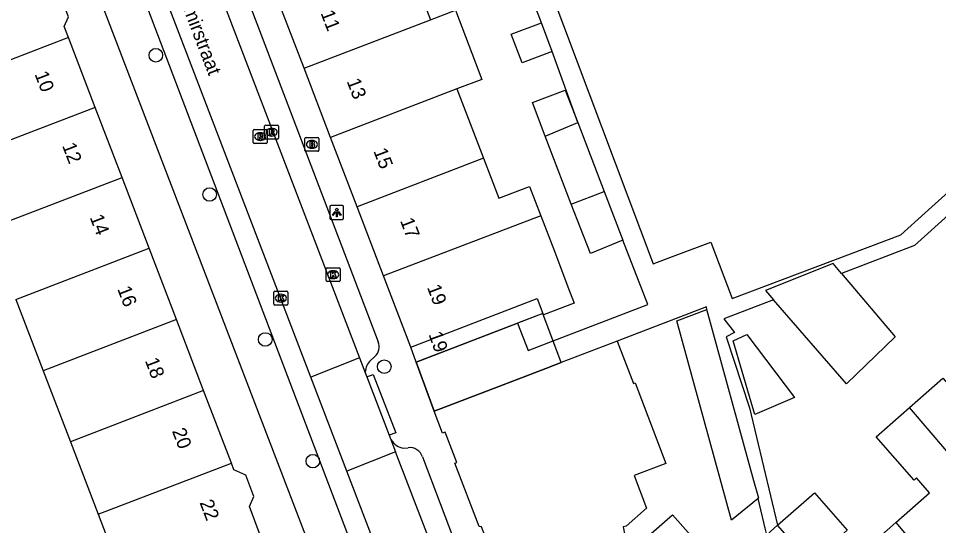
# Model space of a CAD drawing. Extents: x 159961 to 160856, y 382704 to 383353.
# Drawn here: x 160456.8 to 160523.1, y 383056 to 383092.5 of the extents above; entities that cross this region are included whole.
import ezdxf

# ---------------------------------------------------------------- set-up
doc = ezdxf.new("R2010")
doc.units = 0
for name, color, linetype in [('IMGEO_Boom', 7, 'Continuous'), ('IMGEO_Brandkraan', 7, 'Continuous'), ('IMGEO_Kolk', 7, 'Continuous'), ('IMGEO_Lichtpunt', 7, 'Continuous'), ('IMGEO_Openbare_ruimte_label', 7, 'Continuous'), ('IMGEO_Pand', 7, 'Continuous'), ('IMGEO_Pand_nummerreeks', 7, 'Continuous'), ('IMGEO_Pand_overbouw', 7, 'Continuous'), ('IMGEO_Rijbaan_lokaal_open', 7, 'Continuous'), ('IMGEO_Rioolput', 7, 'Continuous'), ('IMGEO_Voetpad_open', 7, 'Continuous')]:
    doc.layers.add(name, color=color, linetype=linetype)

msp = doc.modelspace()

# ---------------------------------------------------------------- linework, layer by layer
at = {"layer": 'IMGEO_Boom'}
for centre in [(160466.702, 383089.855), (160470.576, 383079.834), (160474.58, 383069.407), (160483.146, 383067.451), (160478.005, 383060.653)]:
    msp.add_circle(centre, 0.489, dxfattribs=at)
at = {"layer": 'IMGEO_Brandkraan'}
for p, q in [((160477.44, 383083.016), (160477.44, 383083.868)), ((160477.515, 383083.942), (160478.367, 383083.942)), ((160477.928, 383083.722), (160477.953, 383083.722)), ((160478.441, 383083.868), (160478.441, 383083.016)), ((160477.951, 383083.162), (160477.926, 383083.162)), ((160478.367, 383082.942), (160477.515, 383082.942))]:
    msp.add_line(p, q, dxfattribs=at)
for points in [[(160477.44, 383083.016), (160477.44, 383083.868)], [(160477.515, 383083.942), (160478.367, 383083.942)], [(160478.441, 383083.868), (160478.441, 383083.016)], [(160477.788, 383083.642), (160477.788, 383083.242), (160478.001, 383083.242)], [(160478.019, 383083.642), (160477.788, 383083.642)], [(160477.967, 383083.561), (160477.913, 383083.561), (160477.913, 383083.485)], [(160477.913, 383083.485), (160477.966, 383083.485)], [(160477.975, 383083.409), (160477.913, 383083.409), (160477.913, 383083.328)], [(160477.913, 383083.328), (160477.975, 383083.328)], [(160478.367, 383082.942), (160477.515, 383082.942)]]:
    msp.add_lwpolyline(points, dxfattribs=at)
for centre, radius, start, end in [((160477.517, 383083.866), 0.0765, 91.55205, 178.44795), ((160477.517, 383083.866), 0.0765, 91.55205, 178.44795), ((160478.365, 383083.866), 0.0765, 1.55205, 88.44795), ((160478.365, 383083.866), 0.0765, 1.55205, 88.44795), ((160477.968, 383083.523), 0.0379, 267.82845, 90.93552), ((160477.976, 383083.368), 0.0404, 269.87594, 90.50774), ((160478.007, 383083.493), 0.251, 268.66757, 293.53466), ((160478.023, 383083.497), 0.145, 59.4692, 91.53667), ((160478.048, 383083.544), 0.0922, 285.51372, 58.15012), ((160478.053, 383083.352), 0.105, 301.31148, 78.98903), ((160477.517, 383083.018), 0.0765, 181.55205, 268.44795), ((160477.517, 383083.018), 0.0765, 181.55205, 268.44795), ((160478.365, 383083.018), 0.0765, 271.55205, 358.44795), ((160478.365, 383083.018), 0.0765, 271.55205, 358.44795)]:
    msp.add_arc(centre, radius, start, end, dxfattribs=at)
for centre, major_axis, ratio, start_param, end_param in [((160477.927, 383083.442), (-0.387, 0.002), 0.722429, 4.712389, 7.853982), ((160477.952, 383083.442), (-0.39, 0.002), 0.717154, 1.570796, 4.712389)]:
    msp.add_ellipse(centre, major_axis=major_axis, ratio=ratio, start_param=start_param, end_param=end_param, dxfattribs=at)
at = {"layer": 'IMGEO_Kolk'}
for p, q in [((160478.969, 383073.642), (160478.969, 383074.494)), ((160479.044, 383074.568), (160479.896, 383074.568)), ((160479.97, 383074.494), (160479.97, 383073.642)), ((160479.48, 383073.788), (160479.455, 383073.788)), ((160479.457, 383074.348), (160479.482, 383074.348)), ((160479.896, 383073.568), (160479.044, 383073.568)), ((160475.204, 383071.956), (160475.204, 383072.808)), ((160475.279, 383072.882), (160476.131, 383072.882)), ((160475.692, 383072.662), (160475.717, 383072.662)), ((160476.205, 383072.808), (160476.205, 383071.956)), ((160476.131, 383071.882), (160475.279, 383071.882)), ((160475.715, 383072.102), (160475.69, 383072.102))]:
    msp.add_line(p, q, dxfattribs=at)
for points in [[(160478.969, 383073.642), (160478.969, 383074.494)], [(160479.044, 383074.568), (160479.896, 383074.568)], [(160479.97, 383074.494), (160479.97, 383073.642)], [(160479.29, 383074.268), (160479.413, 383074.268), (160479.413, 383074.117), (160479.543, 383074.268), (160479.707, 383074.268), (160479.561, 383074.117), (160479.714, 383073.868), (160479.562, 383073.868), (160479.477, 383074.032), (160479.413, 383073.965), (160479.413, 383073.868), (160479.29, 383073.868), (160479.29, 383074.268)], [(160479.896, 383073.568), (160479.044, 383073.568)], [(160475.204, 383071.956), (160475.204, 383072.808)], [(160475.279, 383072.882), (160476.131, 383072.882)], [(160475.525, 383072.582), (160475.648, 383072.582), (160475.648, 383072.431), (160475.778, 383072.582), (160475.942, 383072.582), (160475.796, 383072.431), (160475.949, 383072.182), (160475.797, 383072.182), (160475.712, 383072.346), (160475.648, 383072.279), (160475.648, 383072.182), (160475.525, 383072.182), (160475.525, 383072.582)], [(160476.205, 383072.808), (160476.205, 383071.956)], [(160476.131, 383071.882), (160475.279, 383071.882)]]:
    msp.add_lwpolyline(points, dxfattribs=at)
for centre, start, end in [((160479.046, 383074.492), 91.55205, 178.44795), ((160479.046, 383074.492), 91.55205, 178.44795), ((160479.894, 383074.492), 1.55205, 88.44795), ((160479.894, 383074.492), 1.55205, 88.44795), ((160479.046, 383073.644), 181.55205, 268.44795), ((160479.046, 383073.644), 181.55205, 268.44795), ((160479.894, 383073.644), 271.55205, 358.44795), ((160479.894, 383073.644), 271.55205, 358.44795), ((160475.281, 383072.806), 91.55205, 178.44795), ((160475.281, 383072.806), 91.55205, 178.44795), ((160476.129, 383072.806), 1.55205, 88.44795), ((160476.129, 383072.806), 1.55205, 88.44795), ((160475.281, 383071.958), 181.55205, 268.44795), ((160475.281, 383071.958), 181.55205, 268.44795), ((160476.129, 383071.958), 271.55205, 358.44795), ((160476.129, 383071.958), 271.55205, 358.44795)]:
    msp.add_arc(centre, 0.0765, start, end, dxfattribs=at)
for centre, major_axis, ratio, start_param, end_param in [((160479.456, 383074.068), (-0.387, 0.002), 0.722429, 4.712389, 7.853982), ((160479.481, 383074.068), (-0.39, 0.002), 0.717154, 1.570796, 4.712389), ((160475.691, 383072.382), (-0.387, 0.002), 0.722429, 4.712389, 7.853982), ((160475.716, 383072.382), (-0.39, 0.002), 0.717154, 1.570796, 4.712389)]:
    msp.add_ellipse(centre, major_axis=major_axis, ratio=ratio, start_param=start_param, end_param=end_param, dxfattribs=at)
at = {"layer": 'IMGEO_Lichtpunt'}
for p, q in [((160479.228, 383078.946), (160479.228, 383078.139)), ((160479.228, 383078.946), (160479.228, 383078.139)), ((160480.13, 383079.041), (160479.322, 383079.041)), ((160480.13, 383079.041), (160479.322, 383079.041)), ((160480.224, 383078.139), (160480.224, 383078.946)), ((160480.224, 383078.139), (160480.224, 383078.946)), ((160479.322, 383078.045), (160480.13, 383078.045)), ((160479.322, 383078.045), (160480.13, 383078.045))]:
    msp.add_line(p, q, dxfattribs=at)
for points in [[(160479.602, 383078.61), (160479.641, 383078.582), (160479.453, 383078.32), (160479.415, 383078.347), (160479.602, 383078.61)], [(160479.704, 383078.562), (160479.751, 383078.562), (160479.751, 383078.24), (160479.704, 383078.24), (160479.704, 383078.562)], [(160479.814, 383078.582), (160479.852, 383078.609), (160480.039, 383078.347), (160480, 383078.319), (160479.814, 383078.582)]]:
    msp.add_lwpolyline(points, dxfattribs=at)
msp.add_circle((160479.727, 383078.744), 0.0994, dxfattribs=at)
for centre, start, end in [((160479.322, 383078.946), 90, 180), ((160479.322, 383078.946), 90, 180), ((160480.13, 383078.946), 0, 90), ((160480.13, 383078.946), 0, 90), ((160479.322, 383078.139), 180, 270), ((160479.322, 383078.139), 180, 270), ((160480.13, 383078.139), 270, 0), ((160480.13, 383078.139), 270, 360)]:
    msp.add_arc(centre, 0.0946, start, end, dxfattribs=at)
at = {"layer": 'IMGEO_Pand'}
for points in [[(160534.122, 383109.141), (160534.186, 383109.88), (160533.198, 383111.163), (160488.491, 383114.709), (160487.777, 383114.015), (160502.502, 383074.84), (160503.326, 383075.15), (160504.293, 383075.514), (160506.667, 383076.407), (160508.186, 383072.366), (160520.336, 383076.937), (160522.091, 383078.518), (160531.012, 383086.555), (160532.285, 383086.423), (160532.358, 383087.767), (160532.496, 383090.334), (160533.195, 383098.415)], [(160484.566, 383097.39), (160486.474, 383092.408)], [(160460.412, 383091.133), (160460.11, 383091.921), (160460.421, 383092.618), (160459.822, 383094.181), (160459.095, 383094.505), (160458.343, 383096.468)], [(160477.373, 383088.92), (160475.464, 383093.901)], [(160486.474, 383092.408), (160488.266, 383093.095), (160490.175, 383088.113), (160488.383, 383087.426)], [(160477.373, 383088.92), (160486.474, 383092.408)], [(160495.237, 383090.12), (160493.071, 383089.317), (160492.291, 383091.371), (160494.457, 383092.174)], [(160495.237, 383090.12), (160494.457, 383092.174)], [(160460.412, 383091.133), (160450.819, 383087.447)], [(160462.339, 383086.103), (160460.412, 383091.133)], [(160479.282, 383083.938), (160477.373, 383088.92)], [(160488.383, 383087.426), (160479.282, 383083.938)], [(160488.383, 383087.426), (160490.292, 383082.444)], [(160494.731, 383084.036), (160493.821, 383086.456), (160496.174, 383087.34), (160497.073, 383085.006)], [(160462.339, 383086.103), (160452.747, 383082.416)], [(160464.27, 383081.065), (160462.339, 383086.103)], [(160494.731, 383084.036), (160497.073, 383085.006)], [(160497.073, 383085.006), (160498.978, 383080.059)], [(160481.191, 383078.956), (160479.282, 383083.938)], [(160496.612, 383079.152), (160494.731, 383084.036)], [(160490.292, 383082.444), (160481.191, 383078.956)], [(160490.292, 383082.444), (160491.397, 383079.562), (160493.611, 383080.41), (160494.415, 383078.31)], [(160454.677, 383077.379), (160464.27, 383081.065)], [(160466.221, 383075.973), (160464.27, 383081.065)], [(160496.612, 383079.152), (160498.978, 383080.059)], [(160498.978, 383080.059), (160500.327, 383076.556)], [(160500.327, 383076.556), (160497.985, 383075.586), (160496.612, 383079.152)], [(160483.1, 383073.974), (160481.191, 383078.956)], [(160494.415, 383078.31), (160483.1, 383073.974)], [(160494.415, 383078.31), (160495.395, 383075.749), (160496.372, 383073.198), (160496.819, 383072.029), (160494.602, 383071.179), (160494.567, 383071.272)], [(160456.628, 383072.287), (160466.221, 383075.973)], [(160468.188, 383070.838), (160466.221, 383075.973)], [(160516.069, 383074.153), (160515.469, 383074.861), (160510.602, 383072.921), (160511.168, 383072.27)], [(160485.063, 383068.85), (160483.1, 383073.974)], [(160516.069, 383074.153), (160519.934, 383069.591), (160516.42, 383066.225), (160511.168, 383072.27)], [(160456.628, 383072.287), (160458.596, 383067.151)], [(160485.063, 383068.85), (160494.161, 383072.348), (160494.567, 383071.272)], [(160494.567, 383071.272), (160492.745, 383070.572)], [(160510.066, 383057.969), (160508.157, 383056.419), (160504.212, 383070.756), (160506.37, 383071.571)], [(160510.066, 383057.969), (160510.105, 383058.001), (160509.762, 383059.249), (160506.37, 383071.571)], [(160468.188, 383070.838), (160458.596, 383067.151)], [(160470.146, 383065.729), (160468.188, 383070.838)], [(160485.454, 383067.769), (160492.745, 383070.572)], [(160499.915, 383069.294), (160495.894, 383067.753), (160494.781, 383067.327), (160491.401, 383066.032), (160486.731, 383064.243)], [(160499.915, 383069.294), (160501.083, 383066.236), (160501.214, 383066.286), (160503.417, 383060.483), (160501.136, 383059.617), (160502.018, 383057.267), (160500.573, 383055.969), (160500.335, 383055.921), (160500.581, 383054.693), (160500.138, 383054.604), (160500.36, 383053.501), (160501.31, 383054.337), (160501.221, 383054.439), (160503.9, 383056.797), (160505.96, 383054.457)], [(160509.554, 383064.907), (160508.27, 383069.298), (160509.261, 383069.771), (160512.677, 383065.231), (160509.817, 383064.005), (160509.554, 383064.907)], [(160485.454, 383067.769), (160485.063, 383068.85)], [(160458.596, 383067.151), (160460.553, 383062.043)], [(160520.95, 383064.512), (160523.35, 383066.624), (160525.951, 383063.668), (160525.713, 383063.459), (160526.791, 383062.234), (160529.228, 383064.379)], [(160470.146, 383065.729), (160460.553, 383062.043)], [(160472.142, 383060.52), (160470.146, 383065.729)], [(160519.966, 383056.235), (160522.407, 383058.383), (160521.467, 383059.451), (160521.285, 383059.291), (160518.549, 383062.399), (160520.95, 383064.512)], [(160530.16, 383053.768), (160520.95, 383064.512)], [(160494.772, 383045.622), (160493.157, 383047.463), (160493.334, 383047.616), (160490.149, 383055.929), (160489.984, 383055.956), (160488.238, 383060.513), (160488.377, 383060.566), (160487.54, 383062.75), (160487.344, 383062.675), (160486.731, 383064.243)], [(160460.553, 383062.043), (160462.549, 383056.834)], [(160462.549, 383056.834), (160472.142, 383060.52)], [(160474.224, 383055.339), (160473.436, 383057.398), (160473.759, 383058.123), (160473.172, 383059.653), (160472.33, 383060.029), (160472.142, 383060.52)], [(160511.467, 383056.043), (160514.109, 383058.368), (160516.475, 383055.68), (160516.227, 383055.462), (160517.476, 383054.043), (160519.966, 383056.235)], [(160462.549, 383056.834), (160464.547, 383051.62)], [(160515.152, 383051.855), (160511.467, 383056.043)], [(160519.966, 383056.235), (160525.489, 383049.638)]]:
    msp.add_lwpolyline(points, dxfattribs=at)
at = {"layer": 'IMGEO_Pand_overbouw'}
msp.add_lwpolyline([(160494.567, 383071.272), (160485.454, 383067.769), (160486.731, 383064.243), (160491.401, 383066.032), (160494.781, 383067.327), (160495.894, 383067.753)], close=True, dxfattribs=at)
at = {"layer": 'IMGEO_Rijbaan_lokaal_open'}
for points in [[(160463.279, 383115.305), (160481.357, 383068.097)], [(160477.864, 383066.687), (160459.759, 383113.897)], [(160481.357, 383068.097), (160477.864, 383066.687)], [(160481.357, 383068.097), (160481.792, 383066.962)], [(160480.452, 383059.937), (160477.864, 383066.687)], [(160481.792, 383066.962), (160481.889, 383066.71)], [(160481.889, 383066.71), (160483.503, 383062.516)], [(160483.503, 383062.516), (160483.624, 383062.202)], [(160483.624, 383062.202), (160483.958, 383061.336)], [(160483.958, 383061.336), (160480.452, 383059.937)], [(160489.35, 383047.33), (160483.958, 383061.336)], [(160486.314, 383044.65), (160480.452, 383059.937)]]:
    msp.add_lwpolyline(points, dxfattribs=at)
at = {"layer": 'IMGEO_Rioolput'}
for p, q in [((160473.718, 383083.577), (160473.718, 383084.429)), ((160473.793, 383084.503), (160474.645, 383084.503)), ((160474.537, 383083.895), (160474.537, 383084.747)), ((160474.612, 383084.821), (160475.464, 383084.821)), ((160474.719, 383084.429), (160474.719, 383083.577)), ((160475.025, 383084.601), (160475.05, 383084.601)), ((160475.538, 383084.747), (160475.538, 383083.895)), ((160474.229, 383083.723), (160474.204, 383083.723)), ((160474.206, 383084.283), (160474.231, 383084.283)), ((160475.464, 383083.821), (160474.612, 383083.821)), ((160475.048, 383084.041), (160475.023, 383084.041)), ((160474.645, 383083.503), (160473.793, 383083.503))]:
    msp.add_line(p, q, dxfattribs=at)
for points in [[(160473.718, 383083.577), (160473.718, 383084.429)], [(160473.793, 383084.503), (160474.645, 383084.503)], [(160474.537, 383083.895), (160474.537, 383084.747)], [(160474.612, 383084.821), (160475.464, 383084.821)], [(160474.719, 383084.429), (160474.719, 383083.577)], [(160475.126, 383084.519), (160474.874, 383084.521), (160474.874, 383084.121)], [(160475.052, 383084.44), (160474.998, 383084.44), (160474.998, 383084.359)], [(160475.538, 383084.747), (160475.538, 383083.895)], [(160474.307, 383084.201), (160474.055, 383084.203), (160474.055, 383083.803)], [(160474.055, 383083.803), (160474.179, 383083.803), (160474.179, 383083.965), (160474.19, 383083.965)], [(160474.233, 383084.122), (160474.179, 383084.122), (160474.179, 383084.041)], [(160474.179, 383084.041), (160474.231, 383084.041)], [(160474.237, 383083.936), (160474.308, 383083.803), (160474.448, 383083.803), (160474.383, 383083.929)], [(160475.464, 383083.821), (160474.612, 383083.821)], [(160474.874, 383084.121), (160474.998, 383084.121), (160474.998, 383084.283), (160475.009, 383084.283)], [(160474.998, 383084.359), (160475.05, 383084.359)], [(160475.056, 383084.254), (160475.127, 383084.121), (160475.267, 383084.121), (160475.202, 383084.247)], [(160474.645, 383083.503), (160473.793, 383083.503)]]:
    msp.add_lwpolyline(points, dxfattribs=at)
for centre, radius, start, end in [((160473.795, 383084.427), 0.0765, 91.55205, 178.44795), ((160473.795, 383084.427), 0.0765, 91.55205, 178.44795), ((160474.614, 383084.745), 0.0765, 91.55205, 178.44795), ((160474.614, 383084.745), 0.0765, 91.55205, 178.44795), ((160474.643, 383084.427), 0.0765, 1.55205, 88.44795), ((160474.643, 383084.427), 0.0765, 1.55205, 88.44795), ((160475.034, 383084.548), 0.19, 274.7715, 282.96867), ((160475.058, 383084.344), 0.0964, 77.00612, 93.18647), ((160475.072, 383084.401), 0.0378, 276.66336, 79.67722), ((160475.125, 383084.409), 0.109, 350.36119, 89.41601), ((160475.123, 383084.409), 0.112, 277.58423, 350.98172), ((160475.462, 383084.745), 0.0765, 1.55205, 88.44795), ((160475.462, 383084.745), 0.0765, 1.55205, 88.44795), ((160474.189, 383083.912), 0.0533, 26.02933, 88.69889), ((160474.215, 383084.23), 0.19, 274.7715, 282.96867), ((160474.239, 383084.026), 0.0964, 77.00612, 93.18647), ((160474.253, 383084.083), 0.0378, 276.66336, 79.67722), ((160474.306, 383084.091), 0.109, 350.36119, 89.41601), ((160474.304, 383084.091), 0.112, 277.58423, 350.98172), ((160474.288, 383083.876), 0.108, 29.51342, 73.79051), ((160474.614, 383083.897), 0.0765, 181.55205, 268.44795), ((160474.614, 383083.897), 0.0765, 181.55205, 268.44795), ((160475.008, 383084.23), 0.0533, 26.02933, 88.69889), ((160475.107, 383084.194), 0.108, 29.51342, 73.79051), ((160475.462, 383083.897), 0.0765, 271.55205, 358.44795), ((160475.462, 383083.897), 0.0765, 271.55205, 358.44795), ((160473.795, 383083.579), 0.0765, 181.55205, 268.44795), ((160473.795, 383083.579), 0.0765, 181.55205, 268.44795), ((160474.643, 383083.579), 0.0765, 271.55205, 358.44795), ((160474.643, 383083.579), 0.0765, 271.55205, 358.44795)]:
    msp.add_arc(centre, radius, start, end, dxfattribs=at)
for centre, major_axis, ratio, start_param, end_param in [((160475.024, 383084.321), (-0.387, 0.002), 0.722429, 4.712389, 7.853982), ((160475.049, 383084.321), (-0.39, 0.002), 0.717154, 1.570796, 4.712389), ((160474.205, 383084.003), (-0.387, 0.002), 0.722429, 4.712389, 7.853982), ((160474.23, 383084.003), (-0.39, 0.002), 0.717154, 1.570796, 4.712389)]:
    msp.add_ellipse(centre, major_axis=major_axis, ratio=ratio, start_param=start_param, end_param=end_param, dxfattribs=at)
at = {"layer": 'IMGEO_Voetpad_open'}
for points in [[(160449.837, 383127.32), (160482.444, 383042.356), (160483.179, 383041.211)], [(160461.42, 383125.049), (160482.714, 383069.227)], [(160486.314, 383044.65), (160485.994, 383044.724), (160484.611, 383044.657), (160454.903, 383122.684)], [(160494.457, 383092.174), (160493.404, 383094.947), (160492.37, 383097.222)], [(160497.073, 383085.006), (160495.237, 383090.12)], [(160546.031, 383066.356), (160530.296, 383084.243), (160521.309, 383076.166), (160516.069, 383074.153)], [(160492.745, 383070.572), (160493.5, 383068.608), (160495.309, 383069.304), (160502.113, 383071.919), (160500.327, 383076.556)], [(160511.168, 383072.27), (160507.592, 383070.896), (160508.371, 383069.912), (160507.768, 383069.587), (160509.451, 383064.5), (160511.467, 383056.043)], [(160506.37, 383071.571), (160506.353, 383071.748), (160499.915, 383069.294)], [(160482.463, 383068.172), (160482.083, 383067.816)], [(160486.731, 383064.243), (160485.454, 383067.769)], [(160481.889, 383066.71), (160482.355, 383066.887), (160483.97, 383062.693), (160483.503, 383062.516)], [(160484.563, 383061.591), (160484.868, 383061.617)], [(160485.898, 383060.96), (160490.989, 383047.546)], [(160511.467, 383056.043), (160510.688, 383055.357), (160510.574, 383055.835), (160510.066, 383057.969)]]:
    msp.add_lwpolyline(points, dxfattribs=at)
for centre, radius, start, end in [((160481.869, 383068.871), 0.917, 310.38, 22.85459), ((160482.834, 383067.084), 1.049, 135.70501, 186.66196), ((160484.727, 383062.87), 1.29, 211.20282, 262.6937), ((160485, 383060.689), 0.938, 16.82528, 98.11004)]:
    msp.add_arc(centre, radius, start, end, dxfattribs=at)

# ---------------------------------------------------------------- texts
at = {"layer": 'IMGEO_Openbare_ruimte_label'}
msp.add_text('Hendrik Casimirstraat', height=1, rotation=290.97171, dxfattribs=at).set_placement((160465.923, 383100.332))
at = {"layer": 'IMGEO_Pand_nummerreeks'}
for s, rotation, p in [('11', 290.96506, (160478.55, 383092.891)), ('10', 291.07597, (160457.959, 383088.498)), ('13', 290.96432, (160480.43, 383087.984)), ('12', 291.07597, (160459.943, 383083.352)), ('15', 290.96506, (160482.351, 383082.972)), ('14', 291.07597, (160461.929, 383078.197)), ('17', 290.96432, (160484.272, 383077.957)), ('16', 291.07597, (160463.915, 383073.045)), ('19', 290.87837, (160486.213, 383073.161)), ('19', 289.68662, (160486.322, 383069.786)), ('18', 291.07597, (160465.902, 383067.89)), ('20', 291.07597, (160467.854, 383062.822)), ('22', 291.07597, (160469.838, 383057.676))]:
    msp.add_text(s, height=1, rotation=rotation, dxfattribs=at).set_placement(p)

doc.saveas('drawing.dxf')
